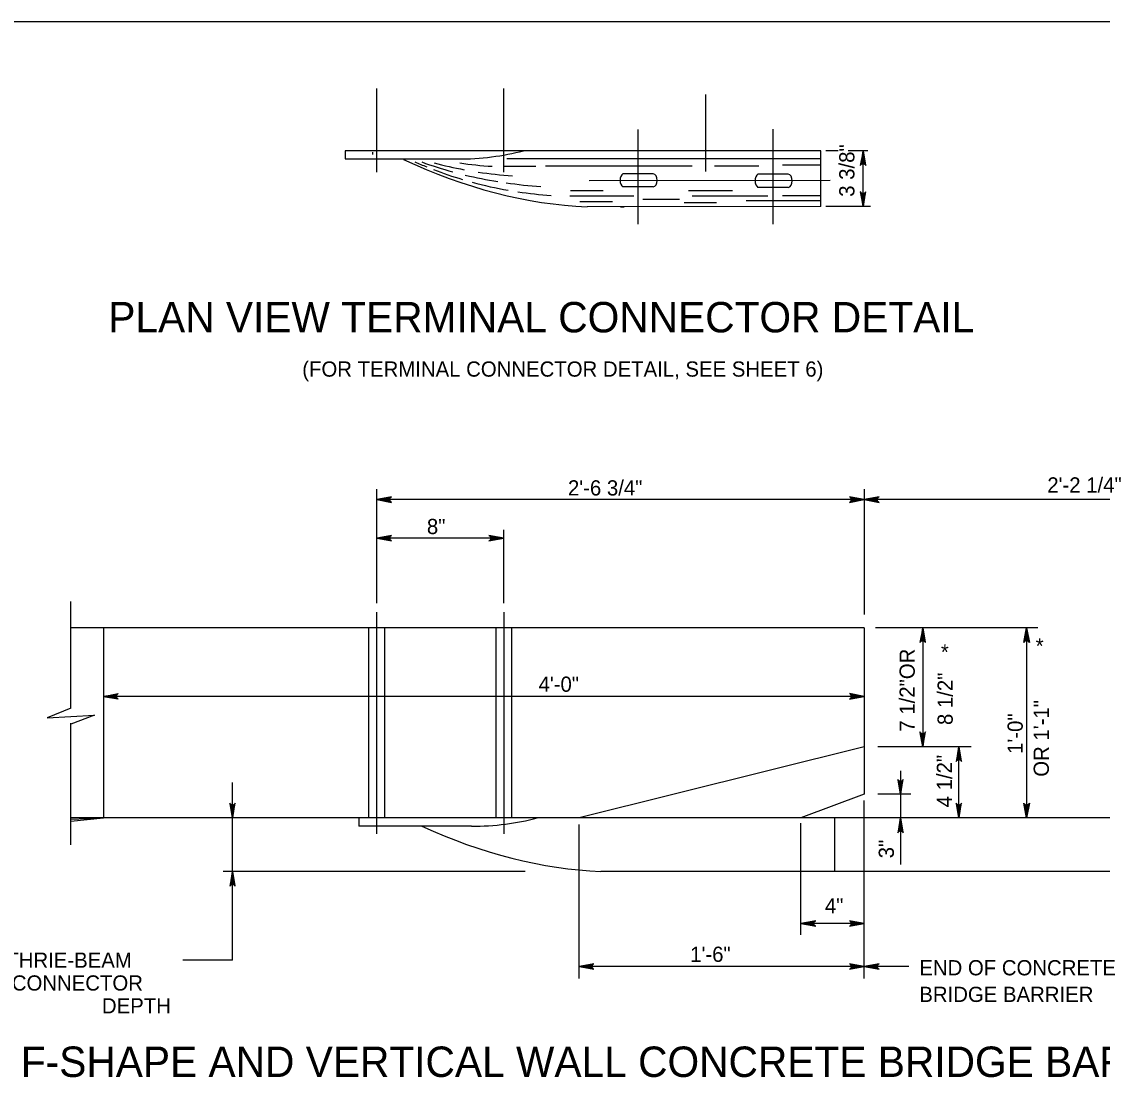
# Model space of a CAD drawing. Extents: x 632007860 to 635435983, y 295418622 to 297794622.
# Drawn here: x 633071236 to 633287745, y 295786093 to 295997622 of the extents above; entities that cross this region are included whole.
import ezdxf

# ---------------------------------------------------------------- set-up
doc = ezdxf.new("R2010")
doc.units = 0
for name, color, linetype in [('1', 7, 'Continuous'), ('8', 7, 'Continuous'), ('S-ABUT', 7, 'Continuous'), ('S-DETL-DIMS', 7, 'Continuous'), ('S-DETL-T120', 7, 'Continuous'), ('S-DETL-T240', 7, 'Continuous'), ('S-STEL', 7, 'Continuous')]:
    doc.layers.add(name, color=color, linetype=linetype)

msp = doc.modelspace()

# ---------------------------------------------------------------- linework, layer by layer
at = {"layer": '1'}
msp.add_line((632888860, 295997622), (633674860, 295997622), dxfattribs=at)
at = {"layer": '8'}
for p, q in [((633142416, 295967465), (633142416, 295984193)), ((633167833, 295967465), (633167833, 295984193)), ((633208310, 295967605), (633208310, 295983037)), ((633194752, 295957026), (633194752, 295976035)), ((633221804, 295957032), (633221804, 295976042)), ((633233233, 295965755), (633184954, 295965749)), ((633142416, 295834901), (633142416, 295879326)), ((633167817, 295879326), (633167817, 295834901))]:
    msp.add_line(p, q, dxfattribs=at)
at = {"layer": 'S-ABUT'}
for p, q in [((633240047, 295876164), (633081100, 295876164)), ((633087647, 295876164), (633087647, 295838064)), ((633240047, 295876164), (633240047, 295842826)), ((633240047, 295852351), (633182897, 295838064)), ((633240047, 295842826), (633227349, 295838064)), ((633227349, 295838064), (633081100, 295838064)), ((633081100, 295837421), (633087647, 295838064)), ((633081100, 295837800), (633087647, 295838064))]:
    msp.add_line(p, q, dxfattribs=at)
at = {"layer": 'S-DETL-DIMS'}
for p, q in [((633234800, 295971753), (633232327, 295971753)), ((633240765, 295971753), (633236799, 295971753)), ((633239800, 295960583), (633239800, 295971753)), ((633241322, 295960583), (633232327, 295960583)), ((633142405, 295881133), (633142405, 295903950)), ((633240047, 295903950), (633240047, 295878818)), ((633240047, 295901855), (633142405, 295901855)), ((633325587, 295901854), (633240047, 295901854)), ((633154155, 295894124), (633142299, 295894124)), ((633167701, 295894124), (633154155, 295894124)), ((633167817, 295881133), (633167817, 295895767)), ((633081100, 295860052), (633081100, 295881460)), ((633274820, 295876164), (633242281, 295876164)), ((633251747, 295876164), (633251747, 295852351)), ((633272561, 295876164), (633272561, 295838064)), ((633240047, 295862436), (633087647, 295862436)), ((633081100, 295832694), (633081100, 295857091)), ((633261473, 295852351), (633242792, 295852351)), ((633258998, 295838064), (633258998, 295852351)), ((633247314, 295847523), (633247314, 295828725)), ((633113488, 295838064), (633113488, 295845143)), ((633249351, 295842826), (633242792, 295842826)), ((633240047, 295805914), (633240047, 295841582)), ((633113488, 295809575), (633113488, 295838064)), ((633182897, 295805914), (633182897, 295836787)), ((633227349, 295814648), (633227349, 295837045)), ((633172090, 295827350), (633111585, 295827350)), ((633240047, 295816921), (633227349, 295816921)), ((633113488, 295809575), (633103553, 295809575)), ((633248948, 295808311), (633182897, 295808311))]:
    msp.add_line(p, q, dxfattribs=at)
for points in [[(633239800, 295971753), (633239245, 295968794), (633239324, 295968908), (633239403, 295969022), (633239502, 295969081), (633239601, 295969140), (633239700, 295969157), (633239800, 295969174), (633239899, 295969157), (633239998, 295969140), (633240097, 295969081), (633240196, 295969022), (633240275, 295968908), (633240354, 295968794), (633239800, 295971753), (633240275, 295968908), (633240196, 295969022), (633239800, 295971753), (633240097, 295969081), (633239998, 295969140), (633239800, 295971753), (633239899, 295969157), (633239800, 295969174), (633239800, 295971753), (633239700, 295969157), (633239601, 295969140), (633239800, 295971753), (633239502, 295969081), (633239403, 295969022), (633239800, 295971753), (633239324, 295968908)], [(633239800, 295960583), (633240354, 295963542), (633240275, 295963428), (633240196, 295963314), (633240097, 295963255), (633239998, 295963197), (633239899, 295963180), (633239800, 295963163), (633239700, 295963180), (633239601, 295963197), (633239502, 295963255), (633239403, 295963314), (633239324, 295963428), (633239245, 295963542), (633239800, 295960583), (633239324, 295963428), (633239403, 295963314), (633239800, 295960583), (633239502, 295963255), (633239601, 295963197), (633239800, 295960583), (633239700, 295963180), (633239800, 295963163), (633239800, 295960583), (633239899, 295963180), (633239998, 295963197), (633239800, 295960583), (633240097, 295963255), (633240196, 295963314), (633239800, 295960583), (633240275, 295963428)], [(633142405, 295901855), (633145364, 295901300), (633145250, 295901379), (633145136, 295901458), (633145077, 295901557), (633145018, 295901656), (633145001, 295901756), (633144984, 295901855), (633145001, 295901954), (633145018, 295902053), (633145077, 295902152), (633145136, 295902252), (633145250, 295902331), (633145364, 295902410), (633142405, 295901855), (633145250, 295902331), (633145136, 295902252), (633142405, 295901855), (633145077, 295902152), (633145018, 295902053), (633142405, 295901855), (633145001, 295901954), (633144984, 295901855), (633142405, 295901855), (633145001, 295901756), (633145018, 295901656), (633142405, 295901855), (633145077, 295901557), (633145136, 295901458), (633142405, 295901855), (633145250, 295901379)], [(633240047, 295901855), (633237088, 295902410), (633237202, 295902331), (633237316, 295902252), (633237375, 295902152), (633237434, 295902053), (633237451, 295901954), (633237468, 295901855), (633237451, 295901756), (633237434, 295901656), (633237375, 295901557), (633237316, 295901458), (633237202, 295901379), (633237088, 295901300), (633240047, 295901855), (633237202, 295901379), (633237316, 295901458), (633240047, 295901855), (633237375, 295901557), (633237434, 295901656), (633240047, 295901855), (633237451, 295901756), (633237468, 295901855), (633240047, 295901855), (633237451, 295901954), (633237434, 295902053), (633240047, 295901855), (633237375, 295902152), (633237316, 295902252), (633240047, 295901855), (633237202, 295902331)], [(633240047, 295901854), (633243007, 295901299), (633242893, 295901378), (633242779, 295901457), (633242720, 295901556), (633242661, 295901655), (633242644, 295901754), (633242627, 295901854), (633242644, 295901953), (633242661, 295902052), (633242720, 295902151), (633242779, 295902251), (633242893, 295902330), (633243007, 295902409), (633240047, 295901854), (633242893, 295902330), (633242779, 295902251), (633240047, 295901854), (633242720, 295902151), (633242661, 295902052), (633240047, 295901854), (633242644, 295901953), (633242627, 295901854), (633240047, 295901854), (633242644, 295901754), (633242661, 295901655), (633240047, 295901854), (633242720, 295901556), (633242779, 295901457), (633240047, 295901854), (633242893, 295901378)], [(633142405, 295894124), (633145364, 295893569), (633145250, 295893648), (633145136, 295893727), (633145077, 295893826), (633145018, 295893925), (633145001, 295894024), (633144984, 295894124), (633145001, 295894223), (633145018, 295894322), (633145077, 295894421), (633145136, 295894520), (633145250, 295894599), (633145364, 295894678), (633142405, 295894124), (633145250, 295894599), (633145136, 295894520), (633142405, 295894124), (633145077, 295894421), (633145018, 295894322), (633142405, 295894124), (633145001, 295894223), (633144984, 295894124), (633142405, 295894124), (633145001, 295894024), (633145018, 295893925), (633142405, 295894124), (633145077, 295893826), (633145136, 295893727), (633142405, 295894124), (633145250, 295893648)], [(633167817, 295894124), (633164858, 295894678), (633164972, 295894599), (633165086, 295894520), (633165145, 295894421), (633165204, 295894322), (633165221, 295894223), (633165238, 295894124), (633165221, 295894024), (633165204, 295893925), (633165145, 295893826), (633165086, 295893727), (633164972, 295893648), (633164858, 295893569), (633167817, 295894124), (633164972, 295893648), (633165086, 295893727), (633167817, 295894124), (633165145, 295893826), (633165204, 295893925), (633167817, 295894124), (633165221, 295894024), (633165238, 295894124), (633167817, 295894124), (633165221, 295894223), (633165204, 295894322), (633167817, 295894124), (633165145, 295894421), (633165086, 295894520), (633167817, 295894124), (633164972, 295894599)], [(633251747, 295876164), (633251192, 295873204), (633251271, 295873318), (633251350, 295873432), (633251449, 295873491), (633251548, 295873550), (633251647, 295873567), (633251747, 295873584), (633251846, 295873567), (633251945, 295873550), (633252044, 295873491), (633252143, 295873432), (633252222, 295873318), (633252301, 295873204), (633251747, 295876164), (633252222, 295873318), (633252143, 295873432), (633251747, 295876164), (633252044, 295873491), (633251945, 295873550), (633251747, 295876164), (633251846, 295873567), (633251747, 295873584), (633251747, 295876164), (633251647, 295873567), (633251548, 295873550), (633251747, 295876164), (633251449, 295873491), (633251350, 295873432), (633251747, 295876164), (633251271, 295873318)], [(633272561, 295876164), (633273115, 295873204), (633273036, 295873318), (633272957, 295873432), (633272858, 295873491), (633272759, 295873550), (633272660, 295873567), (633272561, 295873584), (633272461, 295873567), (633272362, 295873550), (633272263, 295873491), (633272164, 295873432), (633272085, 295873318), (633272006, 295873204), (633272561, 295876164), (633272085, 295873318), (633272164, 295873432), (633272561, 295876164), (633272263, 295873491), (633272362, 295873550), (633272561, 295876164), (633272461, 295873567), (633272561, 295873584), (633272561, 295876164), (633272660, 295873567), (633272759, 295873550), (633272561, 295876164), (633272858, 295873491), (633272957, 295873432), (633272561, 295876164), (633273036, 295873318)], [(633087647, 295862436), (633090607, 295862991), (633090492, 295862912), (633090378, 295862833), (633090320, 295862734), (633090261, 295862634), (633090244, 295862535), (633090227, 295862436), (633090244, 295862337), (633090261, 295862237), (633090320, 295862138), (633090378, 295862039), (633090492, 295861960), (633090607, 295861881), (633087647, 295862436), (633090492, 295861960), (633090378, 295862039), (633087647, 295862436), (633090320, 295862138), (633090261, 295862237), (633087647, 295862436), (633090244, 295862337), (633090227, 295862436), (633087647, 295862436), (633090244, 295862535), (633090261, 295862634), (633087647, 295862436), (633090320, 295862734), (633090378, 295862833), (633087647, 295862436), (633090492, 295862912)], [(633240047, 295862436), (633237088, 295862991), (633237202, 295862912), (633237316, 295862833), (633237375, 295862734), (633237434, 295862634), (633237451, 295862535), (633237468, 295862436), (633237451, 295862337), (633237434, 295862237), (633237375, 295862138), (633237316, 295862039), (633237202, 295861960), (633237088, 295861881), (633240047, 295862436), (633237202, 295861960), (633237316, 295862039), (633240047, 295862436), (633237375, 295862138), (633237434, 295862237), (633240047, 295862436), (633237451, 295862337), (633237468, 295862436), (633240047, 295862436), (633237451, 295862535), (633237434, 295862634), (633240047, 295862436), (633237375, 295862734), (633237316, 295862833), (633240047, 295862436), (633237202, 295862912)], [(633081100, 295860052), (633076337, 295858118), (633085862, 295858695), (633081100, 295856877)], [(633251747, 295852351), (633252301, 295855310), (633252222, 295855196), (633252143, 295855082), (633252044, 295855024), (633251945, 295854965), (633251846, 295854948), (633251747, 295854931), (633251647, 295854948), (633251548, 295854965), (633251449, 295855024), (633251350, 295855082), (633251271, 295855196), (633251192, 295855310), (633251747, 295852351), (633251271, 295855196), (633251350, 295855082), (633251747, 295852351), (633251449, 295855024), (633251548, 295854965), (633251747, 295852351), (633251647, 295854948), (633251747, 295854931), (633251747, 295852351), (633251846, 295854948), (633251945, 295854965), (633251747, 295852351), (633252044, 295855024), (633252143, 295855082), (633251747, 295852351), (633252222, 295855196)], [(633258998, 295852351), (633258443, 295849392), (633258522, 295849506), (633258601, 295849620), (633258701, 295849679), (633258800, 295849737), (633258899, 295849754), (633258998, 295849771), (633259097, 295849754), (633259197, 295849737), (633259296, 295849679), (633259395, 295849620), (633259474, 295849506), (633259553, 295849392), (633258998, 295852351), (633259474, 295849506), (633259395, 295849620), (633258998, 295852351), (633259296, 295849679), (633259197, 295849737), (633258998, 295852351), (633259097, 295849754), (633258998, 295849771), (633258998, 295852351), (633258899, 295849754), (633258800, 295849737), (633258998, 295852351), (633258701, 295849679), (633258601, 295849620), (633258998, 295852351), (633258522, 295849506)], [(633247314, 295842826), (633247869, 295845785), (633247790, 295845671), (633247711, 295845557), (633247611, 295845499), (633247512, 295845440), (633247413, 295845423), (633247314, 295845406), (633247215, 295845423), (633247115, 295845440), (633247016, 295845499), (633246917, 295845557), (633246838, 295845671), (633246759, 295845785), (633247314, 295842826), (633246838, 295845671), (633246917, 295845557), (633247314, 295842826), (633247016, 295845499), (633247115, 295845440), (633247314, 295842826), (633247215, 295845423), (633247314, 295845406), (633247314, 295842826), (633247413, 295845423), (633247512, 295845440), (633247314, 295842826), (633247611, 295845499), (633247711, 295845557), (633247314, 295842826), (633247790, 295845671)], [(633113488, 295838064), (633114042, 295841023), (633113963, 295840909), (633113884, 295840795), (633113785, 295840736), (633113686, 295840677), (633113587, 295840660), (633113488, 295840643), (633113388, 295840660), (633113289, 295840677), (633113190, 295840736), (633113091, 295840795), (633113012, 295840909), (633112933, 295841023), (633113488, 295838064), (633113012, 295840909), (633113091, 295840795), (633113488, 295838064), (633113190, 295840736), (633113289, 295840677), (633113488, 295838064), (633113388, 295840660), (633113488, 295840643), (633113488, 295838064), (633113587, 295840660), (633113686, 295840677), (633113488, 295838064), (633113785, 295840736), (633113884, 295840795), (633113488, 295838064), (633113963, 295840909)], [(633258998, 295838064), (633259553, 295841023), (633259474, 295840909), (633259395, 295840795), (633259296, 295840736), (633259197, 295840677), (633259097, 295840660), (633258998, 295840643), (633258899, 295840660), (633258800, 295840677), (633258701, 295840736), (633258601, 295840795), (633258522, 295840909), (633258443, 295841023), (633258998, 295838064), (633258522, 295840909), (633258601, 295840795), (633258998, 295838064), (633258701, 295840736), (633258800, 295840677), (633258998, 295838064), (633258899, 295840660), (633258998, 295840643), (633258998, 295838064), (633259097, 295840660), (633259197, 295840677), (633258998, 295838064), (633259296, 295840736), (633259395, 295840795), (633258998, 295838064), (633259474, 295840909)], [(633272561, 295838064), (633272006, 295841023), (633272085, 295840909), (633272164, 295840795), (633272263, 295840736), (633272362, 295840678), (633272461, 295840661), (633272561, 295840643), (633272660, 295840661), (633272759, 295840678), (633272858, 295840736), (633272957, 295840795), (633273036, 295840909), (633273115, 295841023), (633272561, 295838064), (633273036, 295840909), (633272957, 295840795), (633272561, 295838064), (633272858, 295840736), (633272759, 295840678), (633272561, 295838064), (633272660, 295840661), (633272561, 295840643), (633272561, 295838064), (633272461, 295840661), (633272362, 295840678), (633272561, 295838064), (633272263, 295840736), (633272164, 295840795), (633272561, 295838064), (633272085, 295840909)], [(633247314, 295838064), (633246759, 295835104), (633246838, 295835218), (633246917, 295835332), (633247016, 295835391), (633247115, 295835450), (633247215, 295835467), (633247314, 295835484), (633247413, 295835467), (633247512, 295835450), (633247611, 295835391), (633247711, 295835332), (633247790, 295835218), (633247869, 295835104), (633247314, 295838064), (633247790, 295835218), (633247711, 295835332), (633247314, 295838064), (633247611, 295835391), (633247512, 295835450), (633247314, 295838064), (633247413, 295835467), (633247314, 295835484), (633247314, 295838064), (633247215, 295835467), (633247115, 295835450), (633247314, 295838064), (633247016, 295835391), (633246917, 295835332), (633247314, 295838064), (633246838, 295835218)], [(633113488, 295827350), (633112933, 295824390), (633113012, 295824504), (633113091, 295824618), (633113190, 295824677), (633113289, 295824736), (633113388, 295824753), (633113488, 295824770), (633113587, 295824753), (633113686, 295824736), (633113785, 295824677), (633113884, 295824618), (633113963, 295824504), (633114042, 295824390), (633113488, 295827350), (633113963, 295824504), (633113884, 295824618), (633113488, 295827350), (633113785, 295824677), (633113686, 295824736), (633113488, 295827350), (633113587, 295824753), (633113488, 295824770), (633113488, 295827350), (633113388, 295824753), (633113289, 295824736), (633113488, 295827350), (633113190, 295824677), (633113091, 295824618), (633113488, 295827350), (633113012, 295824504)], [(633227349, 295816921), (633230308, 295816366), (633230194, 295816445), (633230080, 295816524), (633230021, 295816623), (633229962, 295816723), (633229945, 295816822), (633229928, 295816921), (633229945, 295817020), (633229962, 295817120), (633230021, 295817219), (633230080, 295817318), (633230194, 295817397), (633230308, 295817476), (633227349, 295816921), (633230194, 295817397), (633230080, 295817318), (633227349, 295816921), (633230021, 295817219), (633229962, 295817120), (633227349, 295816921), (633229945, 295817020), (633229928, 295816921), (633227349, 295816921), (633229945, 295816822), (633229962, 295816723), (633227349, 295816921), (633230021, 295816623), (633230080, 295816524), (633227349, 295816921), (633230194, 295816445)], [(633240047, 295816921), (633237088, 295817476), (633237202, 295817397), (633237316, 295817318), (633237375, 295817219), (633237434, 295817120), (633237451, 295817020), (633237468, 295816921), (633237451, 295816822), (633237434, 295816723), (633237375, 295816623), (633237316, 295816524), (633237202, 295816445), (633237088, 295816366), (633240047, 295816921), (633237202, 295816445), (633237316, 295816524), (633240047, 295816921), (633237375, 295816623), (633237434, 295816723), (633240047, 295816921), (633237451, 295816822), (633237468, 295816921), (633240047, 295816921), (633237451, 295817020), (633237434, 295817120), (633240047, 295816921), (633237375, 295817219), (633237316, 295817318), (633240047, 295816921), (633237202, 295817397)], [(633182897, 295808311), (633185857, 295807756), (633185743, 295807835), (633185629, 295807914), (633185570, 295808013), (633185511, 295808112), (633185494, 295808212), (633185477, 295808311), (633185494, 295808410), (633185511, 295808509), (633185570, 295808609), (633185629, 295808708), (633185743, 295808787), (633185857, 295808866), (633182897, 295808311), (633185743, 295808787), (633185629, 295808708), (633182897, 295808311), (633185570, 295808609), (633185511, 295808509), (633182897, 295808311), (633185494, 295808410), (633185477, 295808311), (633182897, 295808311), (633185494, 295808212), (633185511, 295808112), (633182897, 295808311), (633185570, 295808013), (633185629, 295807914), (633182897, 295808311), (633185743, 295807835)], [(633240047, 295808311), (633237088, 295808866), (633237202, 295808787), (633237316, 295808708), (633237375, 295808609), (633237434, 295808509), (633237451, 295808410), (633237468, 295808311), (633237451, 295808212), (633237434, 295808112), (633237375, 295808013), (633237316, 295807914), (633237202, 295807835), (633237088, 295807756), (633240047, 295808311), (633237202, 295807835), (633237316, 295807914), (633240047, 295808311), (633237375, 295808013), (633237434, 295808112), (633240047, 295808311), (633237451, 295808212), (633237468, 295808311), (633240047, 295808311), (633237451, 295808410), (633237434, 295808509), (633240047, 295808311), (633237375, 295808609), (633237316, 295808708), (633240047, 295808311), (633237202, 295808787)], [(633240047, 295808311), (633243007, 295807756), (633242893, 295807835), (633242779, 295807914), (633242720, 295808013), (633242661, 295808112), (633242644, 295808212), (633242627, 295808311), (633242644, 295808410), (633242661, 295808509), (633242720, 295808609), (633242779, 295808708), (633242893, 295808787), (633243007, 295808866), (633240047, 295808311), (633242893, 295808787), (633242779, 295808708), (633240047, 295808311), (633242720, 295808609), (633242661, 295808509), (633240047, 295808311), (633242644, 295808410), (633242627, 295808311), (633240047, 295808311), (633242644, 295808212), (633242661, 295808112), (633240047, 295808311), (633242720, 295808013), (633242779, 295807914), (633240047, 295808311), (633242893, 295807835)]]:
    msp.add_lwpolyline(points, dxfattribs=at)
at = {"layer": 'S-STEL'}
for p, q in [((633142416, 295971903), (633142416, 295974280)), ((633231329, 295971753), (633136078, 295971747)), ((633136078, 295971747), (633136078, 295970101)), ((633231329, 295960579), (633231329, 295971753)), ((633136078, 295970101), (633147726, 295970101)), ((633141601, 295970965), (633141601, 295971497)), ((633147362, 295970101), (633158600, 295970101)), ((633231329, 295970108), (633168468, 295970101)), ((633174222, 295968616), (633167707, 295968616)), ((633205583, 295968646), (633176174, 295968640)), ((633218911, 295968646), (633210065, 295968646)), ((633231329, 295968874), (633223666, 295968874)), ((633197775, 295967145), (633191679, 295967145)), ((633224825, 295967057), (633218729, 295967057)), ((633187713, 295963733), (633181197, 295963733)), ((633197775, 295964496), (633191679, 295964496)), ((633197267, 295964496), (633192187, 295964496)), ((633213650, 295963739), (633204804, 295963739)), ((633224825, 295964409), (633218729, 295964409)), ((633224317, 295964409), (633219237, 295964409)), ((633193887, 295962644), (633181078, 295962644)), ((633189602, 295961516), (633183085, 295961516)), ((633203014, 295961991), (633195673, 295961984)), ((633210459, 295961334), (633203944, 295961334)), ((633220721, 295962651), (633205583, 295962651)), ((633231329, 295961682), (633216415, 295961682)), ((633231329, 295962710), (633223687, 295962710)), ((633231329, 295960579), (633184522, 295960514)), ((633140827, 295838064), (633140827, 295876164)), ((633144005, 295838064), (633144005, 295876164)), ((633166229, 295876164), (633166229, 295838064)), ((633169406, 295876164), (633169406, 295838064)), ((633347331, 295838064), (633138809, 295838064)), ((633138809, 295838064), (633138809, 295836417)), ((633234138, 295827350), (633234138, 295838070)), ((633161349, 295836417), (633138809, 295836417)), ((633342829, 295827350), (633187292, 295827350))]:
    msp.add_line(p, q, dxfattribs=at)
for centre, start, end in [((633182365, 296042111), 245.9713, 247.84038), ((633178687, 296044134), 249.92293, 254.60468), ((633182365, 296042111), 248.90002, 253.30435), ((633174641, 296046034), 254.86039, 259.30149), ((633170534, 296047934), 261.6849, 266.35001), ((633174641, 296046034), 261.3526, 266.35001), ((633178687, 296044134), 256.49028, 261.27182), ((633182365, 296042111), 254.79056, 260.08274), ((633180281, 296043889), 261.3526, 266.35001), ((633182365, 296042111), 261.53517, 266.35001), ((633187897, 296039904), 272.41176, 272.90741)]:
    msp.add_arc(centre, 79461, start, end, dxfattribs=at)
for centre, major_axis, ratio, start_param, end_param in [((633158551, 295983252), (27269, 0), 0.4822531, 4.7141547, 5.2179741), ((633164719, 296039904), (67875, -61215), 0.7464226, 5.0956742, 5.5493346), ((633192045, 295965820), (0, 1443), 0.64, 0.4090626, 2.73253), ((633197700, 295965820), (0, 1329), 0.64, 3.2290764, 6.1957016), ((633219097, 295965733), (0, 1443), 0.64, 0.4090626, 2.73253), ((633224751, 295965733), (0, 1329), 0.64, 3.2290764, 6.1957016), ((633161301, 295849578), (27291, 0), 0.4822531, 4.7141547, 5.2179741), ((633167474, 295906804), (67930, -61265), 0.7464226, 5.1076935, 5.5493346)]:
    msp.add_ellipse(centre, major_axis=major_axis, ratio=ratio, start_param=start_param, end_param=end_param, dxfattribs=at)

# ---------------------------------------------------------------- texts
at = {"layer": 'S-DETL-T120'}
for s, height, p in [('3 3/8"', 3048, (633238070, 295962529)), ('7 1/2"OR', 3048.1, (633250160, 295855360)), ('8 1/2"', 3048.1, (633257768, 295856685)), ('OR 1\'-1"', 3048.1, (633277023, 295846331)), ('1\'-0"', 3048.1, (633271792, 295850903)), ('4 1/2"', 3048.1, (633257620, 295840200)), ('3"', 3048.1, (633245979, 295829986))]:
    msp.add_text(s, height=height, rotation=90, dxfattribs=at).set_placement(p)
for s, height, p in [('(FOR TERMINAL CONNECTOR DETAIL, SEE SHEET 6)', 3048.07, (633127452, 295926488)), ('2\'-6 3/4"', 3048, (633180686, 295902678)), ('2\'-2 1/4"', 3048, (633276710, 295903268)), ('8"', 3048, (633152429, 295894947)), ('*', 3048, (633255391, 295869796)), ('*', 3048, (633274386, 295871017)), ('4\'-0"', 3048.1, (633174788, 295863346)), ('4"', 3048.1, (633232154, 295818949)), ('1\'-6"', 3048.1, (633205169, 295809234)), ('3 3/8" THRIE-BEAM', 3048.07, (633056530, 295808057)), ('END OF CONCRETE', 3048.01, (633251072, 295806539)), ('TERMINAL CONNECTOR', 3048.07, (633047530, 295803485)), ('BRIDGE BARRIER', 3048.01, (633251072, 295801205)), ('DEPTH', 3048.1, (633087323, 295798913))]:
    msp.add_text(s, height=height, dxfattribs=at).set_placement(p)
at = {"layer": 'S-DETL-T240'}
for s, p in [('PLAN VIEW TERMINAL CONNECTOR DETAIL', (633088601, 295935356)), ('PLAN VIEW FOR THRIE-BEAM TO F-SHAPE AND VERTICAL WALL CONCRETE BRIDGE BARRIER', (632938826, 295786179))]:
    msp.add_text(s, height=6096, dxfattribs=at).set_placement(p)

doc.saveas('drawing.dxf')
